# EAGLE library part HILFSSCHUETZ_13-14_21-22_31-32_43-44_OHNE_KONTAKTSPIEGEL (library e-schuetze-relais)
Hilfsschütz mit 2 Schließern und 2 Öffnern ohne Kontaktspiegel
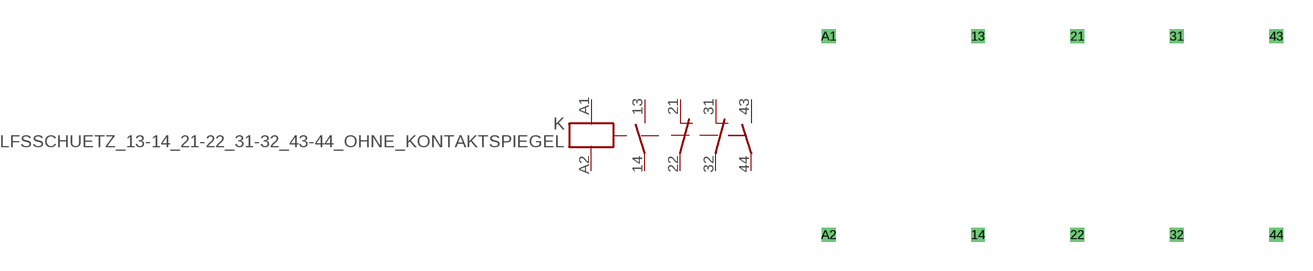
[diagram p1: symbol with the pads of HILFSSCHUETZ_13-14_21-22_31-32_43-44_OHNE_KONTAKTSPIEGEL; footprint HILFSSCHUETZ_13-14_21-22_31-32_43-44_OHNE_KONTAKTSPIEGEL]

Designator prefix K

## HILFSSCHUETZ_13-14_21-22_31-32_43-44_OHNE_KONTAKTSPIEGEL  [HILFSSCHUETZ_13-14_21-22_31-32_43-44_OHNE_KONTAKTSPIEGEL]
13  13  pas
14  14  pas
21  21  pas
22  22  pas
31  31  pas
32  32  pas
43  43  pas
44  44  pas
A1  A1  in
A2  A2  in

## Footprint HILFSSCHUETZ_13-14_21-22_31-32_43-44_OHNE_KONTAKTSPIEGEL (pad centres in mm)
Dummy
drill 0.2 pad 0.6 square: 13 7.62,5.08; 14 7.62,-5.08; 21 12.7,5.08; 22 12.7,-5.08; 31 17.78,5.08; 32 17.78,-5.08; 43 22.86,5.08; 44 22.86,-5.08; A1 0,5.08; A2 0,-5.08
